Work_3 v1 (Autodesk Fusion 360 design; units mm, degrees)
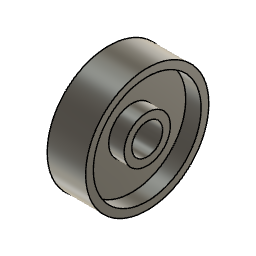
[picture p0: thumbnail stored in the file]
sketch "Sketch1" plane through (0, 0, 0) normal (0, 1, 0) x axis (1, 0, 0)
  line L1 (10, -15) -> (10, -40)
  line L2 (15, -15) -> (10, -15)
  line L3 (15, -40) -> (15, -15)
  line L4 (10, -40) -> (15, -40)
  line L5 (25, -40) -> (15, -40)
  line L6 (25, -35) -> (25, -40)
  line L7 (0, -35) -> (25, -35)
  line L8 (0, -40) -> (0, -35)
  line L9 (10, -40) -> (0, -40)
  line L10 (0, -15) -> (10, -15)
  line L11 (0, -10) -> (0, -15)
  line L12 (25, -10) -> (0, -10)
  line L13 (25, -15) -> (25, -10)
  line L14 (15, -15) -> (25, -15)
  point P1 (0, 0)
  point P12 (25, -10)
  point P7 (25, -35)
  vertical L1
  perpendicular L1 L2
  perpendicular L2 L3
  perpendicular L1 L4
  perpendicular L3 L5
  perpendicular L5 L6
  perpendicular L1 L7
  perpendicular L7 L8
  perpendicular L1 L9
  perpendicular L1 L10
  perpendicular L10 L11
  perpendicular L1 L12
  perpendicular L10 L13
  perpendicular L3 L14
  dimension "d1" distance P1 L12 = 10
  dimension "d2" distance P1 L7 = 35
  dimension "d3" distance P1 L3 = 15
  dimension "d4" distance P1 L10 = 15
  dimension "d5" distance P1 L1 = 10
  dimension "d6" distance P1 L5 = 40
  dimension "d7" distance P1 P12 = 25
  dimension "d8" distance P1 P7 = 25
revolve "Revolve1" sketch "Sketch1" AlongAngle 360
